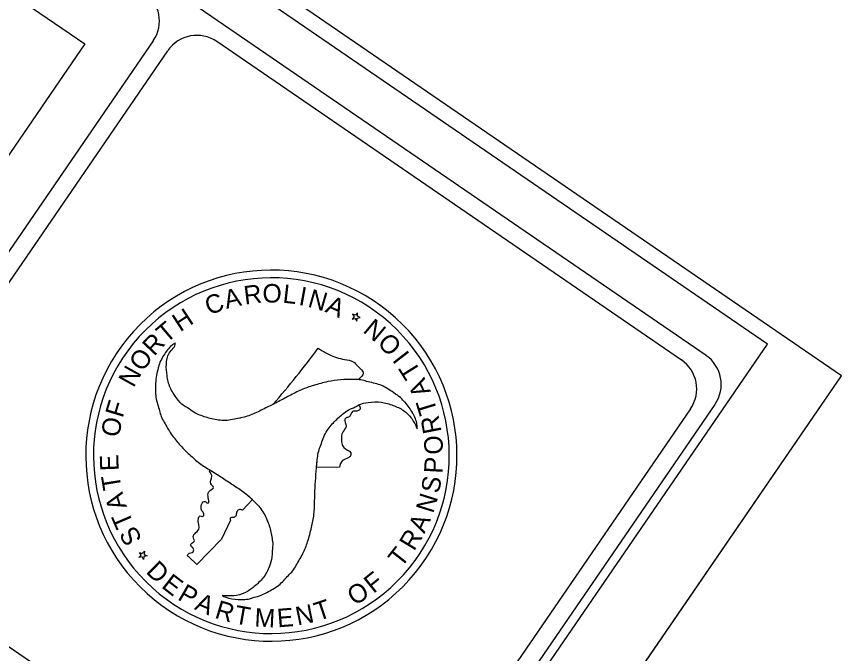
# Model space of a CAD drawing. Extents: x 2312641 to 2338852, y 590461 to 618614.
# Drawn here: x 2335572 to 2338852, y 608804 to 611337 of the extents above; entities that cross this region are included whole.
import ezdxf

# ---------------------------------------------------------------- set-up
doc = ezdxf.new("R2010")
doc.units = 0
for name, color, linetype in [('Exist Other Culture Sign Post Text', 7, 'Continuous'), ('Exist Property Iron Pin Cogo Number', 7, 'Continuous'), ('Exist Roads EOP Other Text', 7, 'Continuous'), ('Exist Utilities Power Joint Use Telephone CELL', 7, 'Continuous'), ('Exist Utilities Power Joint Use Telephone Text', 7, 'Continuous')]:
    doc.layers.add(name, color=color, linetype=linetype)

msp = doc.modelspace()

# ---------------------------------------------------------------- linework, layer by layer
at = {"layer": 'Exist Other Culture Sign Post Text'}
msp.add_line((2325524.4, 590461.2), (2338852.2, 609908.5), dxfattribs=at)
at = {"layer": 'Exist Property Iron Pin Cogo Number'}
for p, q in [((2324877.7, 594842), (2336116.1, 611240.6)), ((2334945.3, 609408.4), (2336173.8, 611201)), ((2336914.5, 610142.9), (2336906, 610133.5)), ((2336906, 610133.5), (2336918.6, 610136.3)), ((2336920.1, 610149.1), (2336908.4, 610153.8)), ((2336908.4, 610153.8), (2336914.5, 610142.9)), ((2336918.6, 610136.3), (2336925.2, 610125.4)), ((2336928.1, 610158.7), (2336920.1, 610149.1)), ((2336925.2, 610125.4), (2336926.3, 610137.7)), ((2336926.3, 610137.7), (2336938.7, 610140.3)), ((2336927.1, 610145.8), (2336928.1, 610158.7)), ((2336938.7, 610140.3), (2336927.1, 610145.8)), ((2337078.9, 610139.2), (2337078.9, 610139.2)), ((2336203.1, 610040), (2336203.3, 610038)), ((2336203.1, 610040), (2336203.3, 610038)), ((2336592.7, 609795.4), (2336592.7, 609795.4)), ((2336855.9, 609544.3), (2336764.6, 609543.2)), ((2336764.6, 609543.2), (2336764.6, 609543.2)), ((2336510.2, 609416.4), (2336470.6, 609373.4)), ((2336422.5, 609333.7), (2336386.4, 609258.3)), ((2336386.4, 609258.3), (2336288.8, 609157.8)), ((2336829.3, 607947.5), (2334981.6, 609213.7)), ((2336058.2, 609185.8), (2336066.9, 609195.4)), ((2336070.8, 609188.3), (2336058.2, 609185.8)), ((2336066.9, 609195.4), (2336060.4, 609205.9)), ((2336060.4, 609205.9), (2336072.1, 609201.2)), ((2336077.4, 609177.4), (2336070.8, 609188.3)), ((2336072.1, 609201.2), (2336080.6, 609210.7)), ((2336078.3, 609189.8), (2336077.4, 609177.4)), ((2336091, 609192.5), (2336078.3, 609189.8)), ((2336080.6, 609210.7), (2336079.3, 609197.7)), ((2336079.3, 609197.7), (2336091, 609192.5)), ((2336288.8, 609157.8), (2336256.8, 609188.6))]:
    msp.add_line(p, q, dxfattribs=at)
for points in [[(2338313.5, 609989.2), (2326418.9, 618140.9)], [(2338216.2, 609971.1), (2336368.4, 611237.3)], [(2326636.7, 592703), (2338350, 609794.5)], [(2337024, 607983.8), (2338252.5, 609776.4)]]:
    msp.add_lwpolyline(points, dxfattribs=at)
for centre, radius, start, end in [((2336000.1, 611320.1), 140, 325.5761, 55.5761), ((2336288.8, 611122.3), 140, 55.5761, 145.5761), ((2336585.2, 609590.7), 738, 47.9972, 227.9972), ((2336585.2, 609590.7), 707.3, 47.9972, 227.9972), ((2336585.2, 609590.7), 738, 227.9972, 47.9972), ((2336585.2, 609590.7), 707.3, 227.9972, 47.9972), ((2333650.8, 612342.4), 3891.2, 319.1148, 323.3208), ((2338136.5, 609856), 140, 325.5761, 55.5761), ((2338233.9, 609874.1), 140, 325.5761, 55.5761), ((2333650.8, 612342.4), 3891.2, 313.6757, 313.7753)]:
    msp.add_arc(centre, radius, start, end, dxfattribs=at)
for points in [[(2336203.3, 610038), (2336189, 610028.6), (2336157.6, 609990.9), (2336136.1, 609943.1), (2336135, 609938.3), (2336128.1, 609910.9), (2336125, 609878.1), (2336126.3, 609823), (2336140.4, 609769.1), (2336147, 609746.7), (2336159.2, 609723.6), (2336187, 609676.6), (2336218.6, 609636.6), (2336260.2, 609594.8), (2336299.1, 609560.9), (2336344, 609531.9), (2336389.7, 609503.2), (2336433.1, 609474.3), (2336477.5, 609444.1), (2336516.8, 609409), (2336520.1, 609405.8), (2336555.5, 609361.2), (2336576.9, 609311.3), (2336588, 609261.9), (2336590.6, 609236.3), (2336588.3, 609205), (2336587.3, 609187.2), (2336577.5, 609150.9), (2336552.5, 609105.4), (2336517.3, 609070.6), (2336479.8, 609045.5), (2336435.6, 609033.5), (2336388.9, 609034.6)], [(2337165.2, 609697.6), (2337164.1, 609713.9), (2337147.2, 609760.3), (2337116.7, 609802.9), (2337113.4, 609806.7), (2337092.7, 609825.9), (2337065.7, 609845.3), (2337017.6, 609872), (2336963.8, 609886.1), (2336941.2, 609892), (2336914.6, 609893), (2336860.3, 609892.4), (2336809.9, 609885.1), (2336753, 609869.8), (2336704.4, 609852.7), (2336656.2, 609828.6), (2336608.9, 609803.5), (2336562.6, 609780.5), (2336513.5, 609756.7), (2336463.8, 609740.5), (2336459.2, 609739.6), (2336402.4, 609730.8), (2336348.6, 609737.4), (2336300.3, 609752.1), (2336277.5, 609763.1), (2336251.4, 609780.8), (2336235.8, 609790.3), (2336210, 609817.2), (2336182.7, 609861.8), (2336170.3, 609909.1), (2336167.6, 609954.2), (2336179.4, 609998.7), (2336203.3, 610038), (2336203.1, 610040)], [(2336771.6, 610017.9), (2336815.2, 609992.8), (2336875.6, 609973.2), (2336910.3, 609964.3), (2336930.3, 609945.7), (2336950.3, 609919.1), (2336931.6, 609893.5)], [(2336931.6, 609893.2), (2336914.6, 609893), (2336860.3, 609892.4), (2336809.9, 609885.1), (2336753, 609869.8), (2336704.4, 609852.7), (2336656.2, 609828.6), (2336608.9, 609803.5), (2336592.7, 609795.4)], [(2336388.9, 609034.6), (2336404.8, 609027.4), (2336453.1, 609018.9), (2336505.2, 609023.8), (2336509.6, 609025.4), (2336537.4, 609033.1), (2336567, 609047), (2336614.5, 609075.5), (2336653.3, 609114.7), (2336669.8, 609131.4), (2336684.2, 609154.6), (2336710.3, 609201.2), (2336729.4, 609248.2), (2336744.8, 609305.5), (2336754.4, 609355.8), (2336757.3, 609409.7), (2336759, 609463.5), (2336762.6, 609515.6), (2336766.9, 609569.1), (2336777.2, 609620.7), (2336779.1, 609625.8), (2336799.9, 609678.9), (2336832, 609721.8), (2336868.7, 609755.9), (2336890.1, 609771.6), (2336918.3, 609784.3), (2336934.5, 609793.5), (2336970.6, 609802.5), (2337022.3, 609803.3), (2337069.8, 609790.6), (2337110.6, 609770.3), (2337143.1, 609738.1), (2337165.2, 609697.6)], [(2336764.6, 609543.2), (2336766.9, 609569.1), (2336777.2, 609620.7), (2336779.1, 609625.8), (2336799.9, 609678.9), (2336832, 609721.8), (2336868.7, 609755.9), (2336890.1, 609771.6), (2336918.3, 609784.3), (2336933.5, 609792.6)], [(2336933.5, 609792.3), (2336938.6, 609778.7), (2336931.8, 609769.8), (2336907.2, 609765.7), (2336894.8, 609744.8), (2336882.8, 609740.9), (2336877.8, 609735.7), (2336882.3, 609708.3), (2336870.4, 609687.3), (2336865.8, 609639.9), (2336872.7, 609623.1), (2336900.9, 609601.5), (2336899.8, 609589.8), (2336890.9, 609582.5), (2336868.3, 609571.1), (2336855.9, 609544.3)], [(2336256.8, 609188.6), (2336252.7, 609190.2), (2336254.1, 609199), (2336274.3, 609208.7), (2336274.7, 609222.5), (2336267.7, 609228.2), (2336266.6, 609240.4), (2336278.3, 609249.1), (2336274.7, 609269.6), (2336280.5, 609280.3), (2336297.2, 609298.8), (2336294.8, 609340.7), (2336301.9, 609351.1), (2336309.8, 609348.1), (2336316.1, 609352.8), (2336306.3, 609378.6), (2336305.9, 609383.4), (2336314.6, 609406.8), (2336322, 609408.4), (2336331.3, 609402.4), (2336335.1, 609403.4), (2336336.1, 609412.7), (2336333.3, 609429.1), (2336338.7, 609449.9), (2336355.1, 609464.2), (2336344.5, 609478.8), (2336348.8, 609509.1), (2336344.6, 609519.9), (2336337.7, 609527.9)], [(2336342.9, 609532.6), (2336344, 609531.9), (2336389.7, 609503.2), (2336433.1, 609474.3), (2336477.5, 609444.1), (2336510.1, 609416.2)], [(2336470.6, 609373.4), (2336458.9, 609376.4), (2336448.8, 609370.1), (2336444.6, 609353.3), (2336436.3, 609345.2), (2336421, 609341.9), (2336422.5, 609333.7)]]:
    msp.add_spline(points, degree=3, dxfattribs=at)
at = {"layer": 'Exist Roads EOP Other Text'}
for p, q in [((2335571.8, 611414.1), (2335843.2, 611228.2)), ((2335843.1, 611228.3), (2334679.7, 609530.7))]:
    msp.add_line(p, q, dxfattribs=at)
at = {"layer": 'Exist Utilities Power Joint Use Telephone CELL'}
msp.add_lwpolyline([(2326149.2, 618614.2), (2312821.5, 599166.9), (2325524.4, 590461.2), (2338852.2, 609908.5)], close=True, dxfattribs=at)
at = {"layer": 'Exist Utilities Power Joint Use Telephone Text'}
msp.add_lwpolyline([(2325368.2, 590788.9), (2338557.5, 610034.1), (2326372.9, 618384.6), (2313183.6, 599139.4)], close=True, dxfattribs=at)

# ---------------------------------------------------------------- texts
at = {"layer": 'Exist Property Iron Pin Cogo Number'}
for s, height, rotation, p in [('R', 73.5, 6.9353, (2336479.9, 610191.4)), ('O', 73.7, 359.8157, (2336549.7, 610199.7)), ('L', 73.4, 353.582, (2336628.1, 610199.5)), ('C', 73.4, 20.7962, (2336337.6, 610148.2)), ('A', 73.5, 13.2992, (2336406.4, 610174)), ('I', 73.7, 349.5926, (2336691.1, 610191)), ('N', 73.6, 343.8925, (2336726.4, 610184)), ('A', 73.6, 336.4606, (2336795.6, 610163.5)), ('H', 73.5, 33.1386, (2336222.5, 610081.1)), ('N', 73.6, 140.2053, (2337047.6, 610095.2)), ('T', 73.8, 40.2233, (2336167.1, 610035)), ('R', 73.6, 46.8729, (2336119, 609983.6)), ('O', 73.3, 132.9573, (2337108.8, 610030.7)), ('O', 73.8, 53.4829, (2336072.7, 609921)), ('I', 73.8, 127.8217, (2337138.1, 609993.7)), ('N', 73.6, 60.981, (2336037.4, 609858.3)), ('T', 73.5, 122.1718, (2337182.7, 609923.6)), ('A', 73.7, 115.0874, (2337220.6, 609845)), ('F', 73.8, 73.0679, (2335993.5, 609738)), ('T', 73.3, 107.0003, (2337246.2, 609765.6)), ('O', 73.7, 80.2148, (2335979.9, 609661.4)), ('R', 73.7, 100.9005, (2337262.7, 609685.8)), ('O', 73.7, 93.7114, (2337269, 609597.1)), ('E', 73.3, 92.1541, (2335978.4, 609530.9)), ('P', 73.6, 87.0194, (2337265.5, 609518.4)), ('T', 73.4, 99.2698, (2335989.7, 609459.8)), ('S', 73.3, 79.8276, (2337251.6, 609438.2)), ('A', 73.8, 106.325, (2336011, 609386.7)), ('N', 73.4, 72.6171, (2337228.2, 609358.3)), ('T', 73.7, 113.3773, (2336038.6, 609320.3)), ('A', 73.4, 65.5855, (2337193.5, 609278.5)), ('S', 73.5, 119.7535, (2336073.3, 609259.4)), ('R', 73.6, 58.8324, (2337152.4, 609208.4)), ('T', 73.4, 51.8757, (2337101.7, 609142.2)), ('D', 73.6, 315.8502, (2336083.3, 609126.7)), ('E', 73.3, 322.1381, (2336144.5, 609068.4)), ('F', 73.5, 38.9665, (2336991, 609040.2)), ('P', 73.6, 329.6705, (2336208.5, 609020.5)), ('O', 73.5, 31.8013, (2336916.1, 608992.3)), ('A', 73.5, 336.2631, (2336276.4, 608980.8)), ('T', 73.5, 18.4976, (2336770.8, 608932.7)), ('R', 73.6, 343.3317, (2336356.5, 608946.6)), ('T', 73.5, 349.9822, (2336434.5, 608924.1)), ('E', 73.4, 4.684, (2336610.6, 608907.7)), ('N', 73.7, 11.6556, (2336689.6, 608915.1)), ('M', 73.4, 357.2173, (2336517, 608910.7))]:
    msp.add_text(s, height=height, rotation=rotation, dxfattribs=at).set_placement(p)

doc.saveas('drawing.dxf')
